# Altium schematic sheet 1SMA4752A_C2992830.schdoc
size 127 x 101 mm
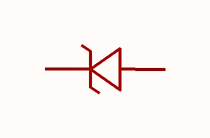
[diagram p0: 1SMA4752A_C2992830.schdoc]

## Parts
D?  1sma4752a_c2992830  [SMA_L4.3-W2.6-LS5.1-RD]  (value not drawn)

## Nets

Not connected (* = marked no-connect by the designer): D? 1(C) 2(A)

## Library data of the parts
D? = 1sma4752a_c2992830: 二极管配置:1个独立式;稳压值(标称值):33V;稳压值(范围):31.3V~34.9V;耗散功率(Pd):1W;; Manufacturer: MDD(辰达半导体); AddInBom: yes; ModelId: 1d20a911e9694ba6aaf6e9207164e4da; ModelTransform: 196.4563,102.362,0,0,0,0,0.001,-0.001,0; Diode Configuration: 1个独立式; Zener Voltage(Nom): 33V; Reverse Leakage Current (Ir): 5uA@25V; Pd - Power Dissipation: 1W; Impedance(Zzt): 45Ω; Operating Junction Temperature Range: -55℃~+150℃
